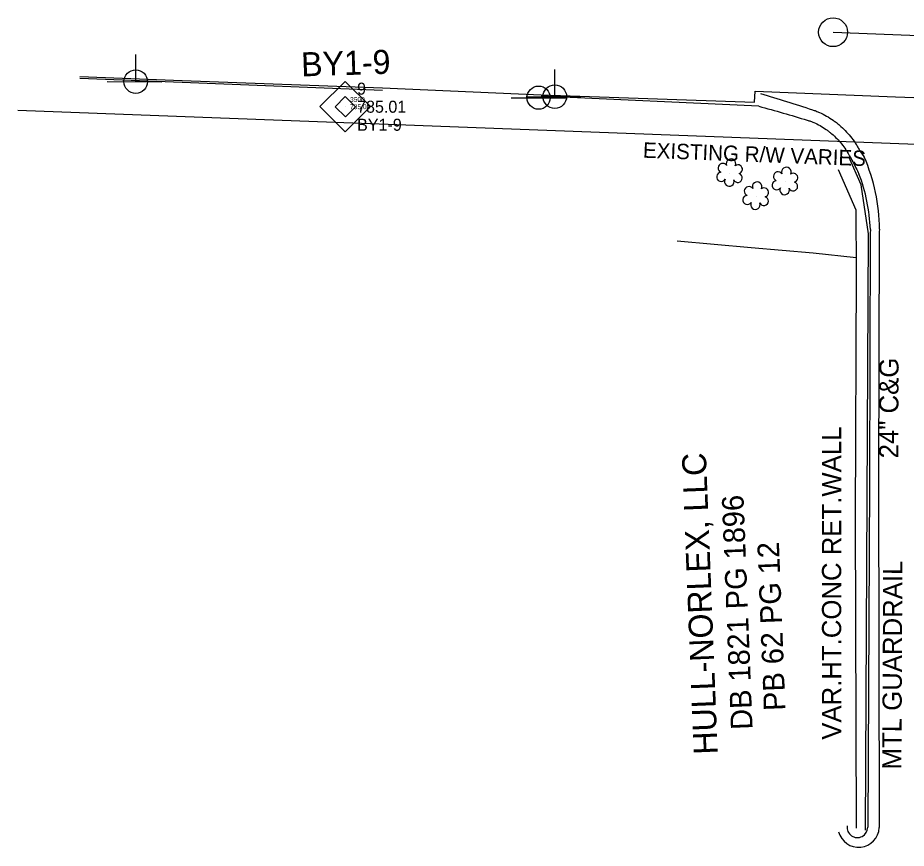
# Model space of a CAD drawing. Extents: x 1627482 to 1629573, y 760826 to 766301.
# Drawn here: x 1628052 to 1628236.7, y 761962.6 to 762135.2 of the extents above; entities that cross this region are included whole.
import ezdxf

# ---------------------------------------------------------------- set-up
doc = ezdxf.new("R2010")
doc.units = 0
for name, color, linetype in [('CTL Secondary Horizontal and Vertical CELL', 7, 'Continuous'), ('CTL Secondary Horizontal and Vertical Cogo Comment', 7, 'Continuous'), ('CTL Secondary Horizontal and Vertical Cogo Elevation', 7, 'Continuous'), ('CTL Secondary Horizontal and Vertical Cogo Number', 7, 'Continuous'), ('CTL Secondary Horizontal and Vertical Text', 7, 'Continuous'), ('Exist Building', 7, 'Continuous'), ('Exist Building Text', 7, 'Continuous'), ('Exist Guardrail', 7, 'Continuous'), ('Exist Guardrail Text', 7, 'Continuous'), ('Exist Horizontal Alignment', 7, 'Continuous'), ('Exist Horizontal Alignment Point', 7, 'Continuous'), ('Exist Property Deed Book Text', 7, 'Continuous'), ('Exist Property Owner Text', 7, 'Continuous'), ('Exist Right of Way Line', 7, 'Continuous'), ('Exist Right of Way Line Text', 7, 'Continuous'), ('Exist Roads Curbs', 7, 'Continuous'), ('Exist Roads Curbs Text', 7, 'Continuous'), ('Exist Roads EOP', 7, 'Continuous'), ('Exist Utilities Power Joint Use Telephone CELL', 7, 'Continuous'), ('Exist Utilities Telephone Pole CELL', 7, 'Continuous'), ('Exist Vegetation Shrub CELL', 7, 'Continuous')]:
    doc.layers.add(name, color=color, linetype=linetype)

msp = doc.modelspace()

# ---------------------------------------------------------------- linework, layer by layer
at = {"layer": 'CTL Secondary Horizontal and Vertical CELL'}
for p, q in [((1628120.06, 762116.75), (1628120.06, 762116.75)), ((1628120.1, 762116.74), (1628120.1, 762116.74))]:
    msp.add_line(p, q, dxfattribs=at)
for points in [[(1628114.84, 762116.77), (1628120.08, 762122.01), (1628125.33, 762116.76), (1628120.09, 762111.52)], [(1628118.02, 762116.75), (1628120.11, 762118.85), (1628122.21, 762116.75), (1628120.12, 762114.65)]]:
    msp.add_lwpolyline(points, close=True, dxfattribs=at)
at = {"layer": 'Exist Building'}
msp.add_lwpolyline([(1628222.57, 762103.7), (1628226.22, 762095.32), (1628226.34, 762082.44), (1628226.13, 762031.17), (1628226.31, 761966.78)], dxfattribs=at)
at = {"layer": 'Exist Guardrail'}
msp.add_lwpolyline([(1628228.28, 761966.41), (1628228.9, 762090.3), (1628227.38, 762100.53), (1628224.8, 762106.33)], dxfattribs=at)
at = {"layer": 'Exist Horizontal Alignment'}
msp.add_line((1628221.51, 762132.23), (1628455.38, 762122.99), dxfattribs=at)
at = {"layer": 'Exist Horizontal Alignment Point'}
msp.add_circle((1628221.51, 762132.23), 3, dxfattribs=at)
at = {"layer": 'Exist Right of Way Line'}
for points in [[(1628200.44, 762110.35), (1628052.03, 762115.98)], [(1628370.51, 762103.91), (1628200.44, 762110.35)]]:
    msp.add_lwpolyline(points, dxfattribs=at)
at = {"layer": 'Exist Roads Curbs'}
for p, q in [((1628206.09, 762116.86), (1628160.85, 762118.97)), ((1628229.26, 762091.26), (1628229.21, 762090.38)), ((1628229.26, 762091.26), (1628229.27, 762091.33))]:
    msp.add_line(p, q, dxfattribs=at)
for points in [[(1628127.82, 762120.13), (1628086.2, 762121.75), (1628064.91, 762122.62)], [(1628229.21, 762090.38), (1628229.06, 762038.55), (1628228.7, 761966.99)], [(1628226.31, 762085.36), (1628217.36, 762086.28), (1628204.51, 762087.44), (1628189.11, 762088.8)]]:
    msp.add_lwpolyline(points, dxfattribs=at)
for centre, major_axis, ratio, start_param, end_param in [((1628194.32, 762090.27), (-24.23, 25.37), 0.993128, 3.981569, 4.31935), ((1628226.56, 761967), (-1.28, 1.72), 0.997426, 0.796655, 4.071101)]:
    msp.add_ellipse(centre, major_axis=major_axis, ratio=ratio, start_param=start_param, end_param=end_param, dxfattribs=at)
msp.add_spline([(1628206.09, 762116.86), (1628216.15, 762113.95), (1628216.83, 762113.73), (1628217.5, 762113.47), (1628218.8, 762112.83), (1628220.05, 762112.04), (1628220.64, 762111.6), (1628221.22, 762111.13), (1628222.3, 762110.12), (1628223.28, 762109.01), (1628224.15, 762107.82), (1628224.53, 762107.21), (1628224.89, 762106.59), (1628226.26, 762104.03), (1628226.88, 762102.79)], degree=3, dxfattribs=at)
at = {"layer": 'Exist Roads EOP'}
for p, q in [((1628127.83, 762120.65), (1628160.83, 762119.19)), ((1628160.83, 762119.19), (1628205.18, 762117.68)), ((1628227.95, 762106.3), (1628227.98, 762106.3)), ((1628231.11, 762090.78), (1628230.97, 762039.06)), ((1628231.16, 762091.3), (1628231.11, 762090.78)), ((1628231.16, 762091.3), (1628231.18, 762091.33)), ((1628231.18, 762091.33), (1628231.18, 762091.34)), ((1628230.97, 762039.06), (1628231.11, 761966.92))]:
    msp.add_line(p, q, dxfattribs=at)
for points in [[(1628064.9, 762123.04), (1628086.23, 762122.17), (1628127.83, 762120.65)], [(1628205.18, 762117.68), (1628205.33, 762119.95), (1628234.48, 762118.79), (1628267, 762117.64), (1628287.52, 762116.88)]]:
    msp.add_lwpolyline(points, dxfattribs=at)
for centre, major_axis, ratio, start_param, end_param in [((1628193.51, 762091.54), (-18.96, 33.11), 0.982732, 4.19326, 4.598792), ((1628226.82, 761967.13), (-1.72, 3.94), 0.997745, 1.40644, 4.253163)]:
    msp.add_ellipse(centre, major_axis=major_axis, ratio=ratio, start_param=start_param, end_param=end_param, dxfattribs=at)
msp.add_spline([(1628206.43, 762119.5), (1628217.2, 762116.12), (1628217.95, 762115.86), (1628218.69, 762115.55), (1628220.14, 762114.82), (1628221.53, 762113.94), (1628222.19, 762113.45), (1628222.83, 762112.92), (1628224.04, 762111.79), (1628225.13, 762110.56), (1628226.09, 762109.25), (1628226.52, 762108.56), (1628226.91, 762107.86), (1628227.95, 762106.3)], degree=3, dxfattribs=at)
at = {"layer": 'Exist Utilities Power Joint Use Telephone CELL'}
for p, q in [((1628076.55, 762121.96), (1628076.55, 762121.96)), ((1628163.65, 762118.85), (1628163.65, 762118.85))]:
    msp.add_line(p, q, dxfattribs=at)
for points in [[(1628070.61, 762121.96), (1628081.95, 762121.92), (1628076.55, 762121.94), (1628076.55, 762127.58)], [(1628157.72, 762118.85), (1628169.05, 762118.81), (1628163.65, 762118.83), (1628163.65, 762124.47)]]:
    msp.add_lwpolyline(points, dxfattribs=at)
for centre in [(1628076.55, 762121.96), (1628163.66, 762118.85)]:
    msp.add_circle(centre, 2.45, dxfattribs=at)
at = {"layer": 'Exist Utilities Telephone Pole CELL'}
for p, q in [((1628154.62, 762118.63), (1628165.96, 762118.63)), ((1628160.3, 762118.63), (1628160.3, 762118.63))]:
    msp.add_line(p, q, dxfattribs=at)
msp.add_circle((1628160.3, 762118.63), 2.41, dxfattribs=at)
at = {"layer": 'Exist Vegetation Shrub CELL'}
for p, q in [((1628200.06, 762102.87), (1628200.06, 762102.87)), ((1628211.57, 762101.13), (1628211.57, 762101.13)), ((1628205.5, 762098.08), (1628205.5, 762098.08))]:
    msp.add_line(p, q, dxfattribs=at)
for centre, radius, start, end in [((1628198.58, 762104), 0.968, 35.8908, 245.4216), ((1628200.29, 762104.91), 0.99, 334.8391, 200.4717), ((1628198.26, 762102.17), 0.955, 95.1099, 327.9534), ((1628201.73, 762103.74), 0.929, 284.4567, 126.0861), ((1628210.09, 762102.25), 0.968, 35.8908, 245.4216), ((1628211.8, 762103.17), 0.99, 334.8391, 200.4717), ((1628213.24, 762102), 0.929, 284.4567, 126.0861), ((1628199.93, 762101.19), 0.984, 151.2797, 21.387), ((1628201.7, 762101.94), 0.937, 204.9913, 73.4601), ((1628205.73, 762100.12), 0.99, 334.8391, 200.4717), ((1628209.77, 762100.42), 0.955, 95.1099, 327.9534), ((1628213.21, 762100.2), 0.937, 204.9913, 73.4601), ((1628204.02, 762099.2), 0.968, 35.8908, 245.4216), ((1628207.17, 762098.95), 0.929, 284.4567, 126.0861), ((1628211.44, 762099.44), 0.984, 151.2797, 21.387), ((1628203.7, 762097.37), 0.955, 95.1099, 327.9534), ((1628207.14, 762097.15), 0.937, 204.9913, 73.4601), ((1628205.37, 762096.39), 0.984, 151.2797, 21.387)]:
    msp.add_arc(centre, radius, start, end, dxfattribs=at)

# ---------------------------------------------------------------- texts
at = {"layer": 'CTL Secondary Horizontal and Vertical Cogo Comment'}
msp.add_text('BY1-9', height=2.5, dxfattribs=at).set_placement((1628122.56, 762111.75))
at = {"layer": 'CTL Secondary Horizontal and Vertical Cogo Elevation'}
for s, height, p in [('785.01', 2.5, (1628122.56, 762115.5)), ('785.09', 1, (1628121.1, 762116.24))]:
    msp.add_text(s, height=height, dxfattribs=at).set_placement(p)
at = {"layer": 'CTL Secondary Horizontal and Vertical Cogo Number'}
for s, height, p in [('9', 2.5, (1628122.56, 762119.25)), ('3500', 1, (1628121.1, 762117.74))]:
    msp.add_text(s, height=height, dxfattribs=at).set_placement(p)
at = {"layer": 'CTL Secondary Horizontal and Vertical Text'}
msp.add_text('BY1-9', height=5, rotation=1.7713, dxfattribs=at).set_placement((1628111, 762123.04))
at = {"layer": 'Exist Building Text'}
msp.add_text('VAR.HT.CONC RET.WALL', height=4, rotation=90, dxfattribs=at).set_placement((1628223.2, 761985.19))
at = {"layer": 'Exist Guardrail Text'}
msp.add_text('MTL GUARDRAIL', height=4, rotation=89.712, dxfattribs=at).set_placement((1628235.71, 761979.01))
at = {"layer": 'Exist Property Deed Book Text'}
for s, p in [('DB 1821 PG 1896', (1628204.79, 761987.34)), ('PB 62 PG 12', (1628211.63, 761991.28))]:
    msp.add_text(s, height=4.5, rotation=92.2582, dxfattribs=at).set_placement(p)
at = {"layer": 'Exist Property Owner Text'}
msp.add_text('HULL-NORLEX, LLC', height=5, rotation=92.2582, dxfattribs=at).set_placement((1628197.54, 761982.19))
at = {"layer": 'Exist Right of Way Line Text'}
msp.add_text('EXISTING R/W VARIES', height=3.2, rotation=357.8295, dxfattribs=at).set_placement((1628181.94, 762106.16))
at = {"layer": 'Exist Roads Curbs Text'}
msp.add_text('24" C&G', height=4, rotation=89.8331, dxfattribs=at).set_placement((1628235.07, 762043.66))

doc.saveas('drawing.dxf')
